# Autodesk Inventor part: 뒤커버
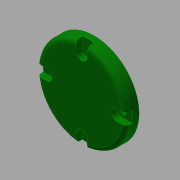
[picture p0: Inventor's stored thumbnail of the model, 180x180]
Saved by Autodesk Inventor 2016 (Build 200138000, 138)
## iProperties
Created: 2019-01
Part Number: 뒤커버
Material: 알루미늄 6061
Document SubType Name: Modeling
Designer: mduedu
Density: 2.71 g/cm^3
Appearance: 진녹색
Mass: 71.8557 g
Surface Area: 92.0216 cm^2
Volume: 26.515 cm^3
Author: mduedu
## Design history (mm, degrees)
sketch "스케치1"
  geometry: L1 (0, 0)-(9, 0); L2 (9, 0)-(9, 32); L3 (9, 32)-(0, 32); L4 (0, 32)-(0, 0); L5 (9, 0)-(12, 0); L6 (12, 0)-(12, 20); L7 (12, 20)-(9, 20); L8 (9, 20)-(9, 0)
  constraints: 16 end point, 4 parallel, 2 horizontal, 2 perpendicular
  dimensions: "d0" = 12 distance between parallel lines of L6 L4; "d2" = 64 diameter of L3 L1; "d3" = 40 diameter of L7 L5; "d4" = 3 distance between parallel lines of L6 L2
revolve "회전1" sketch "스케치1" stored, may be unused: angle "d5" = 90 deg
sketch "스케치4"
  geometry: C1 r 15 at (0, 0); 1 further point
  constraints: 1 centre point, 1 coincident
  dimensions: "d24" = 30 diameter of C1
extrude "돌출1" cut sketch "스케치4" distance "d25" = 6; taper "d26" = 0 deg
fillet "모깎기4" dims "d27" = 3
fillet "모깎기3" dims "d18" = 3
chamfer "모따기2" distance "d28" = 1; stored, may be unused: second distance "d29" = 2, angle "d30" = 45 deg
sketch "스케치3" dims "d19" = 50
  geometry: 6 further points
  constraints: 2 vertical alignment, 1 coincident, 7 other
  dimensions: "d22" = 360 deg dimension on point (0, 0) point (0, 25) (derived)
sketch "스케치5"
  geometry: 4 further points
  constraints: 4 other
hole "구멍1" sketch "스케치5" at (-25, 0), (0, -25), (25, 0), (0, 25) diameter "d31" = 4.5; stored, may be unused: countersink angle "d35" = 90 deg, drill point angle "d37" = 0 deg; dims "d32" = 6, "d33" = 8, "d34" = 4.6, "d36" = 8
sketch "스케치6"
  geometry: L1 (-4, 0)-(-4, 6.749); L2 (4, 0)-(4, 6.749); A1 r 4 centre (0, 0) between (0, 4) and (-4, 0) reference; A2 r 32 centre (0, -25) between (-4, 6.749) and (4, 6.749) reference; A3 r 4 centre (0, 0) between (-4, 0) and (4, 0); A4 r 32 centre (0, -25) between (4, 6.749) and (-4, 6.749); A5 r 4 centre (0, 0) between (4, 0) and (-4, 0); 1 further point
  constraints: 10 point on circle, 4 end point, 3 centre point, 2 coincident, 2 tangent, 1 parallel, 1 vertical
extrude "돌출2" cut sketch "스케치6" stored distance "d38" = 10; taper "d39" = 0 deg
node "솔리드1"
pattern_circular "원형 패턴1" dims angle "d41" = 360 deg
